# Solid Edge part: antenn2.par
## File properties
Author: XPPRESP3
Template: Normal.par
Last saved by: Blackblade
Revision: 18
Application: Solid Edge
Accuracy: 0.990
Material: (None)
Face Style: Model Default
Fill Style: Default
Coef. of Thermal Exp: 0.0
Thermal Conductivity: 0.0
Specific Heat: 0.0
Modulus of Elasticity: 0.0
Poission's Ratio: 0.0
Yield Stress: 0.0
Ultimate Stress: 0.0
Elongation: 0.0
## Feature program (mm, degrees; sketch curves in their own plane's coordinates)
sketch for "unnamed RevolvedProtrusion 1" plane through (0, 0, 0) normal (0, -1, 0) x-axis (1, 0, 0)
revolve "unnamed RevolvedProtrusion 1" add finite 360 deg
sketch used by "unnamed Protrusion 1" plane through (0, 0, 26.51) normal (0, 0, -1) x-axis (-1, 0, 0)
extrude "unnamed Protrusion 1" add finite 2.4916 along -normal
sketch for "RevolvedProtrusion_3" plane through (0, 0, 29.0017) normal (0, 0, 1) x-axis (-1, 0, 0)
revolve "RevolvedProtrusion_3" add finite 90 deg about sketch line (-0.3641, 0.2571) -> (-0.3641, -0.2118)
sketch for "ExtrudedProtrusion_4" plane through (0.3641, 0, 29.3658) normal (1, 0, 0) x-axis (0, 1, 0)
extrude "ExtrudedProtrusion_4" add finite 1.277 along +normal
sketch for "RevolvedProtrusion_5" plane through (1.6411, 0, 29.3658) normal (1, 0, 0) x-axis (0, 1, 0)
  circle centre (0, 0) radius 0.35
revolve "RevolvedProtrusion_5" add finite 90 deg about sketch line (-0.3626, 0.3102) -> (-0.3626, -0.2258)
helix protrusion "HelixProtrusion_2"  NumberOfTurns = 5
sketch for "RevolvedProtrusion_6" plane through (2.0037, -0.3626, 40.9036) normal (0, -1, 0) x-axis (1, 0, 0)
revolve "RevolvedProtrusion_6" add finite 90 deg about sketch line (-0.3501, 0.3399) -> (-0.3501, -0.2915)
sketch for "unnamed Protrusion 2" plane through (1.6536, -0.7126, 40.9036) normal (-1, 0, 0) x-axis (0, 1, 0)
  circle centre (0, 0) radius 0.35
extrude "unnamed Protrusion 2" add to key point along +normal
sketch for "RevolvedProtrusion_7" plane through (0.3641, -0.7126, 40.9036) normal (-1, 0, 0) x-axis (0, 1, 0)
  circle centre (0, 0) radius 0.35
revolve "RevolvedProtrusion_7" add finite 90 deg about sketch line (0.3482, -0.37) -> (-0.3257, -0.37)
sketch for "ExtrudedProtrusion_6" plane through (-0.0059, -0.7126, 41.2736) normal (0, 0, 1) x-axis (1, 0, 0)
extrude "ExtrudedProtrusion_6" add finite 30 along +normal
sketch for "unnamed RevolvedProtrusion 2" plane through (0.3441, -0.7126, 81.2962) normal (0, -1, 0) x-axis (1, 0, 0)
revolve "unnamed RevolvedProtrusion 2" add finite 360 deg
sketch for "ExtrudedProtrusion_7" plane through (0, 0, 26.51) normal (0, 0, -1) x-axis (0, 1, 0)
extrude "ExtrudedProtrusion_7" add finite 0.2 along +normal
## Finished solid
Body 1: solid body, 13 faces, 12 edges, 0 vertices.
  Faces by surface: cylinder 5, torus 4, sphere 2, plane 1, spline 1
  Edges by curve: circle 12
Bounding box of the edges (mm; curved faces can reach further): 4.660 x 4.613 x 44.964, from (-2.3064, -2.3064, 26.31) to (2.3537, 2.3064, 71.2736).
Cylindrical faces by radius (mm): R0.35 x4, R2.3064 x1
Toroidal faces (ring radius, tube radius in mm): R0.3501 r0.35 x1, R0.3626 r0.35 x1, R0.3641 r0.35 x1, R0.37 r0.35 x1
Spherical faces by radius (mm): R1 x1, R2.3458 x1
Planar faces by outward normal: -z 1
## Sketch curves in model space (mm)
circle centre (0, 0, 26.51) radius 0.35
line (2.3064, 0, 26.51) -> (0, 0, 26.51)
line (0, 0, 26.51) -> (0, 0, 28.4278)
arc centre (0, 0, 26.082) radius 2.3458 from (0, 0, 28.4278) through (1.4998, 0, 27.8857) to (2.3064, 0, 26.51)
circle centre (0.3641, 0, 29.3658) radius 0.35
arc centre (-0.0059, -0.7126, 72.2104) radius 1 from (-0.0059, -0.7126, 73.2104) through (0.983, -0.7126, 72.359) to (0.3441, -0.7126, 71.2736)
line (-0.0059, -0.7126, 71.2736) -> (0.3441, -0.7126, 71.2736)
line (-0.0059, -0.7126, 71.2736) -> (-0.0059, -0.7126, 73.2104)
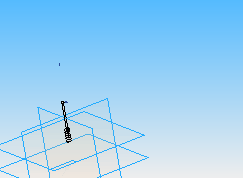
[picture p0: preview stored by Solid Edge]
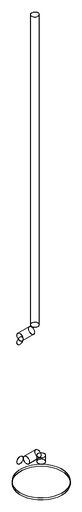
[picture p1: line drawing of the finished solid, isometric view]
